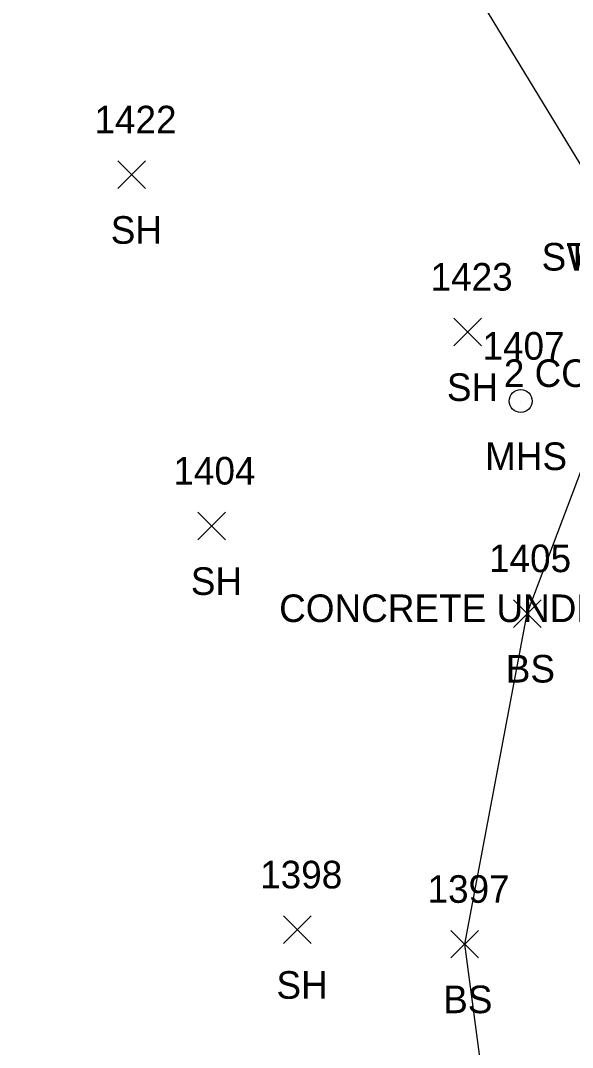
# Model space of a CAD drawing. Extents: x 1653908 to 1654393, y 539913 to 544256.
# Drawn here: x 1653996.7 to 1654036.7, y 541556.9 to 541631.4 of the extents above; entities that cross this region are included whole.
import ezdxf

# ---------------------------------------------------------------- set-up
doc = ezdxf.new("R2010")
doc.units = 0
for name, color, linetype in [('L_A', 7, 'Continuous'), ('L_I', 7, 'Continuous'), ('L_TIC', 7, 'Continuous'), ('LAWA', 7, 'Continuous'), ('LELB', 7, 'Continuous'), ('S_C', 7, 'Continuous'), ('U_A', 7, 'Continuous'), ('U_C', 7, 'Continuous'), ('U_I', 7, 'Continuous'), ('USMH', 7, 'Continuous')]:
    doc.layers.add(name, color=color, linetype=linetype)

msp = doc.modelspace()

# ---------------------------------------------------------------- linework, layer by layer
at = {"layer": 'L_TIC'}
for points in [[(1654003.744, 541619.195), (1654005.744, 541621.195)], [(1654005.744, 541619.195), (1654003.744, 541621.195)], [(1654028.107, 541607.8), (1654030.107, 541609.8)], [(1654030.107, 541607.8), (1654028.107, 541609.8)], [(1654009.546, 541593.742), (1654011.546, 541595.742)], [(1654011.546, 541593.742), (1654009.546, 541595.742)], [(1654032.422, 541587.392), (1654034.422, 541589.392)], [(1654034.422, 541587.392), (1654032.422, 541589.392)], [(1654015.752, 541564.471), (1654017.752, 541566.471)], [(1654017.752, 541564.471), (1654015.752, 541566.471)], [(1654027.888, 541563.425), (1654029.888, 541565.425)], [(1654029.888, 541563.425), (1654027.888, 541565.425)]]:
    msp.add_lwpolyline(points, dxfattribs=at)
at = {"layer": 'LAWA'}
msp.add_lwpolyline([(1654038.913, 541618.252), (1654026.279, 541639.027), (1654008.006, 541653.162), (1653988.111, 541677.483), (1653964.639, 541704.447), (1653928.638, 541724.558)], dxfattribs=at)
at = {"layer": 'LELB'}
msp.add_lwpolyline([(1654027.089, 541497.132), (1654026.771, 541513.404), (1654027.633, 541533.26), (1654033.539, 541540.162), (1654033.701, 541541.772), (1654031.605, 541544.072), (1654028.888, 541564.425), (1654033.422, 541588.392), (1654040.341, 541606.742), (1654044.362, 541608.705)], dxfattribs=at)
at = {"layer": 'USMH'}
for p, q in [((1654032.946, 541603.793), (1654032.946, 541603.793)), ((1654033.779, 541603.793), (1654033.779, 541603.793))]:
    msp.add_line(p, q, dxfattribs=at)
msp.add_circle((1654032.946, 541603.793), 0.833, dxfattribs=at)

# ---------------------------------------------------------------- texts
at = {"layer": 'L_A'}
for s, p in [('SH', (1654003.232, 541615.195)), ('STONE', (1654034.457, 541613.252)), ('WDR', (1654036.275, 541613.252)), ('SH', (1654027.595, 541603.8)), ('SH', (1654009.035, 541589.742)), ('BS', (1654031.863, 541583.392)), ('SH', (1654015.241, 541560.471)), ('BS', (1654027.329, 541559.425))]:
    msp.add_text(s, height=2, dxfattribs=at).set_placement(p)
at = {"layer": 'L_I'}
for s, p in [('1422', (1654002.051, 541623.195)), ('1423', (1654026.414, 541611.8)), ('1404', (1654007.775, 541597.742)), ('1405', (1654030.65, 541591.392)), ('1398', (1654014.06, 541568.471)), ('1397', (1654026.195, 541567.425))]:
    msp.add_text(s, height=2, dxfattribs=at).set_placement(p)
at = {"layer": 'S_C'}
msp.add_text('CONCRETE UNDERGROUND MARKER', height=2, dxfattribs=at).set_placement((1654015.438, 541587.775))
at = {"layer": 'U_A'}
msp.add_text('MHS', height=2, dxfattribs=at).set_placement((1654030.363, 541598.793))
at = {"layer": 'U_C'}
msp.add_text('2 CONDUITS ALONG BEAM', height=2, dxfattribs=at).set_placement((1654031.724, 541604.814))
msp.add_text('2 CONDUITS ALONG BEAM', height=2, dxfattribs=at).set_placement((1654031.724, 541604.814))
at = {"layer": 'U_I'}
msp.add_text('1407', height=2, dxfattribs=at).set_placement((1654030.174, 541606.793))

doc.saveas('drawing.dxf')
